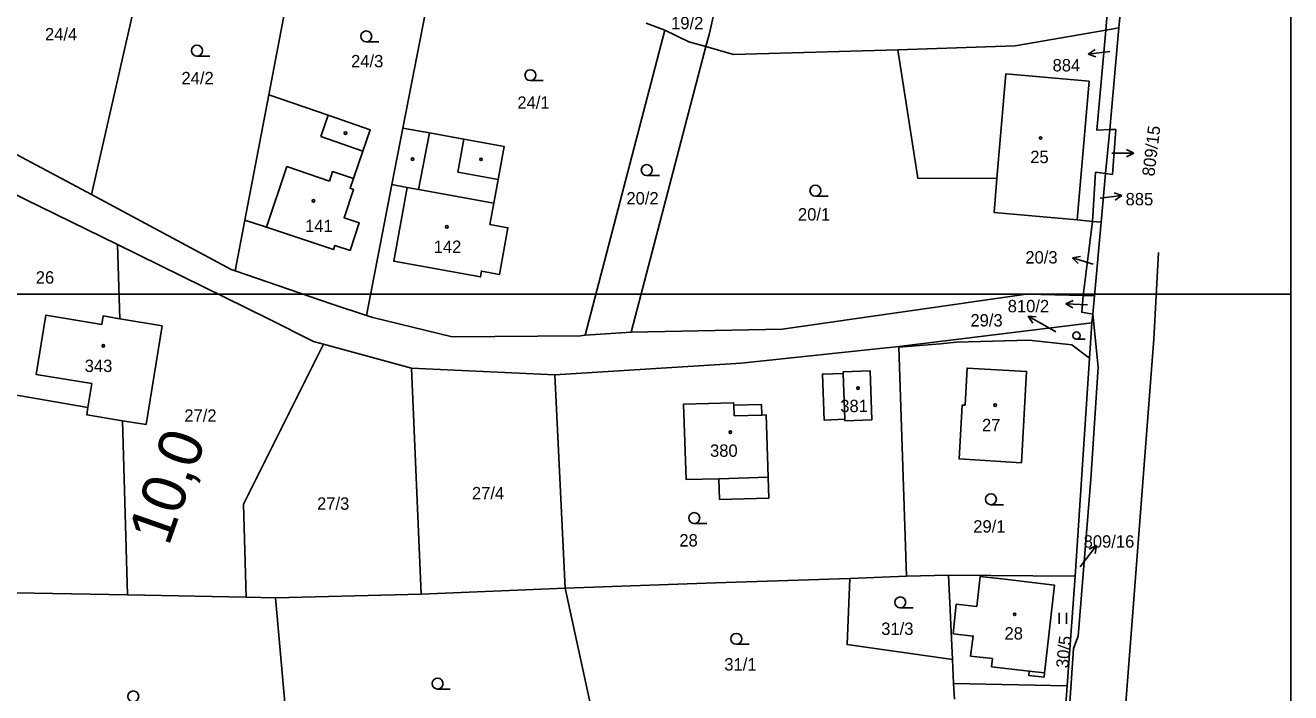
# Model space of a CAD drawing. Extents: x -553916 to -552953, y -1067470 to -1066637.
# Drawn here: x -553473.7 to -553300, y -1067154.7 to -1067063.1 of the extents above; entities that cross this region are included whole.
import ezdxf

# ---------------------------------------------------------------- set-up
doc = ezdxf.new("R2010")
doc.units = 0
for name, color, linetype in [('Hranice parcel', 7, 'Continuous'), ('Návěst místo trati', 7, 'Continuous'), ('Parcelní čísla', 7, 'Continuous'), ('Pop  PČ popisy', 7, 'Continuous'), ('Vnitřní kresba', 7, 'Continuous'), ('Vrstva 1', 7, 'Continuous'), ('Značky budov', 7, 'Continuous'), ('Značky kultur', 7, 'Continuous')]:
    doc.layers.add(name, color=color, linetype=linetype)

msp = doc.modelspace()

# ---------------------------------------------------------------- linework, layer by layer
at = {"layer": 'Hranice parcel'}
for p, q in [((-553454.79, -1067042.97), (-553464.58, -1067086.32)), ((-553440.26, -1067072.6), (-553435.72, -1067048.88)), ((-553417.43, -1067054.37), (-553421.87, -1067077.19)), ((-553325.39, -1067063.72), (-553324.77, -1067056.36)), ((-553322.94, -1067056.53), (-553323.57, -1067063.41)), ((-553385.89, -1067063.74), (-553388.47, -1067062.79)), ((-553396.84, -1067105.64), (-553385.89, -1067063.74)), ((-553325.39, -1067063.72), (-553323.57, -1067063.41)), ((-553323.57, -1067063.41), (-553324.84, -1067077.36)), ((-553380.27, -1067066), (-553390.52, -1067105.19)), ((-553440.26, -1067072.6), (-553443.55, -1067089.82)), ((-553432.11, -1067075.42), (-553440.26, -1067072.6)), ((-553421.87, -1067077.19), (-553423.38, -1067084.95)), ((-553418.2, -1067077.85), (-553421.87, -1067077.19)), ((-553325.4, -1067083.43), (-553324.84, -1067077.36)), ((-553324.84, -1067077.36), (-553324, -1067077.38)), ((-553324, -1067077.38), (-553324.47, -1067083.56)), ((-553325.4, -1067083.43), (-553326.01, -1067090.1)), ((-553324.47, -1067083.56), (-553325.4, -1067083.43)), ((-553461.02, -1067093.19), (-553475.9, -1067085.87)), ((-553423.38, -1067084.95), (-553426.87, -1067102.9)), ((-553423.38, -1067084.95), (-553421.28, -1067085.32)), ((-553444.89, -1067096.79), (-553443.55, -1067089.82)), ((-553443.55, -1067089.82), (-553440.59, -1067090.8)), ((-553328.49, -1067100.17), (-553327.22, -1067089.99)), ((-553327.22, -1067089.99), (-553326.01, -1067090.1)), ((-553326.01, -1067090.1), (-553326.94, -1067100.2)), ((-553460.73, -1067103.36), (-553461.02, -1067093.19)), ((-553328.49, -1067100.17), (-553326.94, -1067100.2)), ((-553326.94, -1067100.2), (-553327.17, -1067102.72)), ((-553463.01, -1067102.98), (-553460.73, -1067103.36)), ((-553327.17, -1067102.72), (-553327.28, -1067103.91)), ((-553327.17, -1067102.72), (-553326.43, -1067110.03)), ((-553460.73, -1067103.36), (-553454.89, -1067104.33)), ((-553454.89, -1067104.33), (-553457.09, -1067117.9)), ((-553327.28, -1067103.91), (-553353.79, -1067107.17)), ((-553327.6, -1067108.78), (-553327.28, -1067103.91)), ((-553396.84, -1067105.64), (-553390.52, -1067105.19)), ((-553420.68, -1067110.16), (-553432.77, -1067106.87)), ((-553353.79, -1067107.29), (-553348.07, -1067106.79)), ((-553353.79, -1067107.29), (-553353.79, -1067107.17)), ((-553352.74, -1067138.71), (-553353.79, -1067107.29)), ((-553330.06, -1067106.96), (-553327.6, -1067108.78)), ((-553419.36, -1067141.18), (-553420.68, -1067110.16)), ((-553401.02, -1067111.06), (-553420.68, -1067110.16)), ((-553329.6, -1067138.69), (-553327.6, -1067108.78)), ((-553399.58, -1067140.36), (-553401.02, -1067111.06)), ((-553465.08, -1067115.55), (-553464.57, -1067112.27)), ((-553459.64, -1067141.29), (-553460.33, -1067117.37)), ((-553457.09, -1067117.9), (-553460.33, -1067117.37)), ((-553360.51, -1067139.02), (-553352.74, -1067138.71)), ((-553346.98, -1067138.59), (-553352.74, -1067138.71)), ((-553329.6, -1067138.69), (-553346.98, -1067138.59)), ((-553346.98, -1067138.59), (-553346.42, -1067150.14)), ((-553330.68, -1067153.79), (-553329.6, -1067138.69)), ((-553479.18, -1067140.92), (-553459.64, -1067141.29)), ((-553459.64, -1067141.29), (-553443.39, -1067141.6)), ((-553439.36, -1067141.68), (-553419.36, -1067141.18)), ((-553419.36, -1067141.18), (-553399.58, -1067140.36)), ((-553393.46, -1067168.37), (-553399.58, -1067140.36)), ((-553443.39, -1067141.6), (-553439.36, -1067141.68)), ((-553439.36, -1067141.68), (-553436.84, -1067169.66)), ((-553346.42, -1067150.14), (-553346.27, -1067153.44)), ((-553346.27, -1067153.44), (-553346.16, -1067155.58)), ((-553330.68, -1067153.79), (-553346.27, -1067153.44)), ((-553331.55, -1067165.94), (-553330.68, -1067153.79))]:
    msp.add_line(p, q, dxfattribs=at)
for points in [[(-553376.72, -1067050.6), (-553379.84, -1067064.34), (-553380.27, -1067066)], [(-553385.89, -1067063.74), (-553382.59, -1067065.35), (-553380.27, -1067066)], [(-553325.39, -1067063.72), (-553337.84, -1067065.87), (-553353.94, -1067066.44)], [(-553324.84, -1067077.36), (-553326.62, -1067077.46), (-553325.39, -1067063.72)], [(-553380.27, -1067066), (-553376.47, -1067067.08), (-553353.94, -1067066.44)], [(-553353.94, -1067066.44), (-553351.19, -1067084.05), (-553340.32, -1067084.09), (-553340.72, -1067088.77), (-553329.33, -1067089.8), (-553327.22, -1067089.99)], [(-553440.59, -1067090.8), (-553431.38, -1067093.86), (-553431.19, -1067093.29), (-553429.1, -1067093.99), (-553427.84, -1067090.19), (-553429.93, -1067089.5), (-553428.64, -1067085.61), (-553429.11, -1067085.44), (-553428.66, -1067084.11), (-553427.35, -1067080.34), (-553426.35, -1067077.41), (-553432.11, -1067075.42)], [(-553421.28, -1067085.32), (-553423.12, -1067095.46), (-553411.21, -1067097.62), (-553411.07, -1067096.83), (-553408.61, -1067097.28), (-553407.45, -1067090.88), (-553409.91, -1067090.44), (-553409.38, -1067087.48), (-553408.79, -1067084.24), (-553407.97, -1067079.71), (-553413.48, -1067078.71), (-553418.2, -1067077.85)], [(-553477.96, -1067079.63), (-553476.25, -1067080.06), (-553464.58, -1067086.32)], [(-553327.22, -1067089.99), (-553326.77, -1067083.26), (-553325.4, -1067083.43)], [(-553475.9, -1067085.87), (-553480.97, -1067091.73), (-553477.55, -1067113.39), (-553465.08, -1067115.55)], [(-553464.58, -1067086.32), (-553445.44, -1067096.58), (-553444.89, -1067096.79)], [(-553432.77, -1067106.87), (-553434.15, -1067106.49), (-553440.39, -1067103.34), (-553461.02, -1067093.19)], [(-553328.17, -1067237.16), (-553327.73, -1067221.42), (-553325.1, -1067188.21), (-553321.08, -1067135.94), (-553318.8, -1067106.18), (-553318.16, -1067094.26)], [(-553444.89, -1067096.79), (-553431.55, -1067101.35), (-553426.87, -1067102.9)], [(-553390.52, -1067105.19), (-553369.78, -1067104.8), (-553336.26, -1067099.99), (-553328.49, -1067100.17)], [(-553327.17, -1067102.72), (-553328.68, -1067102.47), (-553328.49, -1067100.17)], [(-553464.57, -1067112.27), (-553472.2, -1067111.01), (-553470.87, -1067102.88), (-553463.19, -1067104.15), (-553463.01, -1067102.98)], [(-553426.87, -1067102.9), (-553426, -1067103.18), (-553415.09, -1067105.85), (-553397.48, -1067105.69), (-553396.84, -1067105.64)], [(-553348.07, -1067106.79), (-553345.91, -1067106.58), (-553335.92, -1067106.31), (-553330.06, -1067106.96)], [(-553443.39, -1067141.6), (-553443.73, -1067128.82), (-553432.77, -1067106.87)], [(-553353.79, -1067107.17), (-553375.43, -1067109.45), (-553401.02, -1067111.06)], [(-553344.7, -1067115.25), (-553344.41, -1067110.13), (-553336.25, -1067110.59), (-553336.93, -1067123.13), (-553345.51, -1067122.62), (-553345.09, -1067115.22), (-553344.7, -1067115.25)], [(-553326.43, -1067110.03), (-553327.44, -1067125.38), (-553329.15, -1067146.93), (-553329.8, -1067148.66), (-553330.31, -1067156.1), (-553330.14, -1067159), (-553331.52, -1067175.88)], [(-553361.2, -1067117.16), (-553364.03, -1067117.31), (-553364.27, -1067110.96), (-553361.43, -1067110.88), (-553361.44, -1067110.67), (-553357.72, -1067110.52), (-553357.47, -1067117.24), (-553361.19, -1067117.38), (-553361.2, -1067117.16)], [(-553378.41, -1067128.18), (-553378.49, -1067125.33), (-553382.97, -1067125.46), (-553383.32, -1067115.09), (-553376.46, -1067114.89), (-553376.45, -1067115.25), (-553372.64, -1067115.16), (-553372.6, -1067116.6), (-553371.98, -1067116.58), (-553371.71, -1067125.13), (-553371.65, -1067128.01), (-553378.41, -1067128.18)], [(-553460.33, -1067117.37), (-553465.24, -1067116.57), (-553465.08, -1067115.55)], [(-553399.58, -1067140.36), (-553378.93, -1067139.61), (-553360.51, -1067139.02)], [(-553346.42, -1067150.14), (-553360.9, -1067148.11), (-553360.51, -1067139.02)], [(-553340.91, -1067150.03), (-553343.94, -1067149.68), (-553343.57, -1067146.94), (-553346.35, -1067146.61), (-553345.9, -1067142.54), (-553343.1, -1067142.86), (-553342.64, -1067138.76), (-553339.67, -1067139.1), (-553332.42, -1067139.93), (-553333.66, -1067150.86), (-553333.79, -1067151.98), (-553333.86, -1067152.58), (-553335.94, -1067152.34), (-553335.88, -1067151.74), (-553341.05, -1067151.15), (-553340.91, -1067150.03)]]:
    msp.add_lwpolyline(points, dxfattribs=at)
at = {"layer": 'Pop  PČ popisy'}
for p, q in [((-553327.79, -1067067.02), (-553326.86, -1067066.4)), ((-553324.81, -1067066.65), (-553327.79, -1067067.02)), ((-553327.79, -1067067.02), (-553326.73, -1067067.39)), ((-553324.55, -1067080.64), (-553321.55, -1067080.64)), ((-553321.55, -1067080.64), (-553322.55, -1067080.14)), ((-553321.55, -1067080.64), (-553322.55, -1067081.14)), ((-553326.15, -1067086.81), (-553323.17, -1067086.44)), ((-553323.17, -1067086.44), (-553324.23, -1067086.07)), ((-553323.17, -1067086.44), (-553324.1, -1067087.06)), ((-553329.96, -1067094.99), (-553328.86, -1067094.81)), ((-553327.09, -1067095.87), (-553329.96, -1067094.99)), ((-553329.96, -1067094.99), (-553329.15, -1067095.76)), ((-553330.88, -1067101.31), (-553329.85, -1067100.86)), ((-553327.88, -1067101.47), (-553330.88, -1067101.31)), ((-553330.88, -1067101.31), (-553329.9, -1067101.86)), ((-553333.41, -1067104.49), (-553336.04, -1067103.03)), ((-553336.04, -1067103.03), (-553334.92, -1067103.08)), ((-553336.04, -1067103.03), (-553335.4, -1067103.96)), ((-553332.23, -1067105.14), (-553333.41, -1067104.49)), ((-553328.49, -1067136.88), (-553326.64, -1067134.52)), ((-553326.64, -1067134.52), (-553327.65, -1067135)), ((-553326.64, -1067134.52), (-553326.86, -1067135.61)), ((-553328.9, -1067137.42), (-553328.49, -1067136.88))]:
    msp.add_line(p, q, dxfattribs=at)
at = {"layer": 'Vnitřní kresba'}
for p, q in [((-553340.32, -1067084.09), (-553339.1, -1067069.75)), ((-553327.66, -1067070.75), (-553339.1, -1067069.75)), ((-553327.66, -1067070.75), (-553329.33, -1067089.8)), ((-553433.12, -1067078.35), (-553432.11, -1067075.42)), ((-553427.35, -1067080.34), (-553433.12, -1067078.35)), ((-553418.2, -1067077.85), (-553419.71, -1067085.61)), ((-553414.3, -1067083.24), (-553413.48, -1067078.71)), ((-553440.59, -1067090.8), (-553437.81, -1067082.45)), ((-553437.81, -1067082.45), (-553431.95, -1067084.47)), ((-553431.95, -1067084.47), (-553431.5, -1067083.14)), ((-553431.5, -1067083.14), (-553428.66, -1067084.11)), ((-553408.79, -1067084.24), (-553414.3, -1067083.24)), ((-553419.71, -1067085.61), (-553421.28, -1067085.32)), ((-553409.38, -1067087.48), (-553419.71, -1067085.61)), ((-553361.43, -1067110.88), (-553361.2, -1067117.16)), ((-553376.41, -1067116.71), (-553376.45, -1067115.25)), ((-553372.6, -1067116.6), (-553376.41, -1067116.71)), ((-553378.49, -1067125.33), (-553371.71, -1067125.13)), ((-553333.79, -1067151.98), (-553335.88, -1067151.74))]:
    msp.add_line(p, q, dxfattribs=at)
at = {"layer": 'Vrstva 1'}
for points in [[(-553300, -1066816.27), (-553300, -1067100), (-553800, -1067100), (-553800, -1066816.27)], [(-553800, -1067410.27), (-553800, -1067100), (-553300, -1067100), (-553300, -1067410.27)]]:
    msp.add_lwpolyline(points, dxfattribs=at)
at = {"layer": 'Značky budov'}
for centre in [(-553429.74, -1067077.88), (-553334.33, -1067078.55), (-553420.53, -1067081.45), (-553411.14, -1067081.47), (-553434.14, -1067087.18), (-553415.82, -1067090.74), (-553462.98, -1067107.08), (-553359.39, -1067112.9), (-553340.56, -1067115.24), (-553376.91, -1067118.93), (-553337.89, -1067143.96)]:
    msp.add_circle(centre, 0.175, dxfattribs=at)
at = {"layer": 'Značky kultur'}
for p, q in [((-553426.89, -1067065.35), (-553425.14, -1067065.35)), ((-553450.12, -1067067.3), (-553448.37, -1067067.3)), ((-553404.36, -1067070.67), (-553402.61, -1067070.67)), ((-553388.39, -1067083.7), (-553386.64, -1067083.7)), ((-553365.24, -1067086.53), (-553363.49, -1067086.53)), ((-553329.4, -1067106.18), (-553328.22, -1067106.18)), ((-553341.15, -1067128.9), (-553339.4, -1067128.9)), ((-553381.87, -1067131.48), (-553380.12, -1067131.48)), ((-553353.59, -1067143.07), (-553351.84, -1067143.07)), ((-553331.76, -1067145.27), (-553331.76, -1067143.77)), ((-553330.76, -1067145.27), (-553330.76, -1067143.77)), ((-553376.09, -1067148.07), (-553374.34, -1067148.07)), ((-553417.1, -1067154.21), (-553415.35, -1067154.21))]:
    msp.add_line(p, q, dxfattribs=at)
for centre, radius in [((-553426.89, -1067064.6), 0.75), ((-553450.12, -1067066.55), 0.75), ((-553404.36, -1067069.92), 0.75), ((-553388.39, -1067082.95), 0.75), ((-553365.24, -1067085.78), 0.75), ((-553329.4, -1067105.68), 0.502), ((-553341.15, -1067128.15), 0.75), ((-553381.87, -1067130.73), 0.75), ((-553353.59, -1067142.32), 0.75), ((-553376.09, -1067147.32), 0.75), ((-553417.1, -1067153.46), 0.75), ((-553458.87, -1067155.22), 0.75)]:
    msp.add_circle(centre, radius, dxfattribs=at)

# ---------------------------------------------------------------- texts
at = {"layer": 'Návěst místo trati'}
msp.add_text('10,0', height=6, rotation=70.7132, dxfattribs=at).set_placement((-553454.01, -1067134.71))
at = {"layer": 'Parcelní čísla'}
for s, p in [('19/2', (-553385.04, -1067063.61)), ('24/4', (-553470.98, -1067065.14)), ('24/3', (-553428.97, -1067068.84)), ('884', (-553332.68, -1067069.4)), ('24/2', (-553452.25, -1067071.17)), ('24/1', (-553406.15, -1067074.54)), ('25', (-553335.75, -1067081.99)), ('20/2', (-553391.18, -1067087.67)), ('885', (-553322.66, -1067087.79)), ('20/1', (-553367.63, -1067089.88)), ('141', (-553435.29, -1067091.46)), ('142', (-553417.63, -1067094.33)), ('20/3', (-553336.42, -1067095.78)), ('26', (-553472.25, -1067098.54)), ('810/2', (-553338.84, -1067102.48)), ('29/3', (-553343.96, -1067104.43)), ('343', (-553465.53, -1067110.68)), ('381', (-553361.82, -1067116.19)), ('27/2', (-553451.86, -1067117.51)), ('27', (-553342.37, -1067118.81)), ('380', (-553379.7, -1067122.32)), ('27/4', (-553412.38, -1067128.16)), ('27/3', (-553433.64, -1067129.59)), ('29/1', (-553343.57, -1067132.73)), ('28', (-553383.91, -1067134.64)), ('809/16', (-553328.42, -1067134.8)), ('31/3', (-553356.2, -1067146.78)), ('28', (-553339.28, -1067147.42)), ('31/1', (-553377.74, -1067151.67))]:
    msp.add_text(s, height=1.7, dxfattribs=at).set_placement(p)
for s, rotation, p in [('809/15', 83, (-553318.72, -1067083.87)), ('30/5', 84, (-553330.54, -1067151.4))]:
    msp.add_text(s, height=1.7, rotation=rotation, dxfattribs=at).set_placement(p)

doc.saveas('drawing.dxf')
